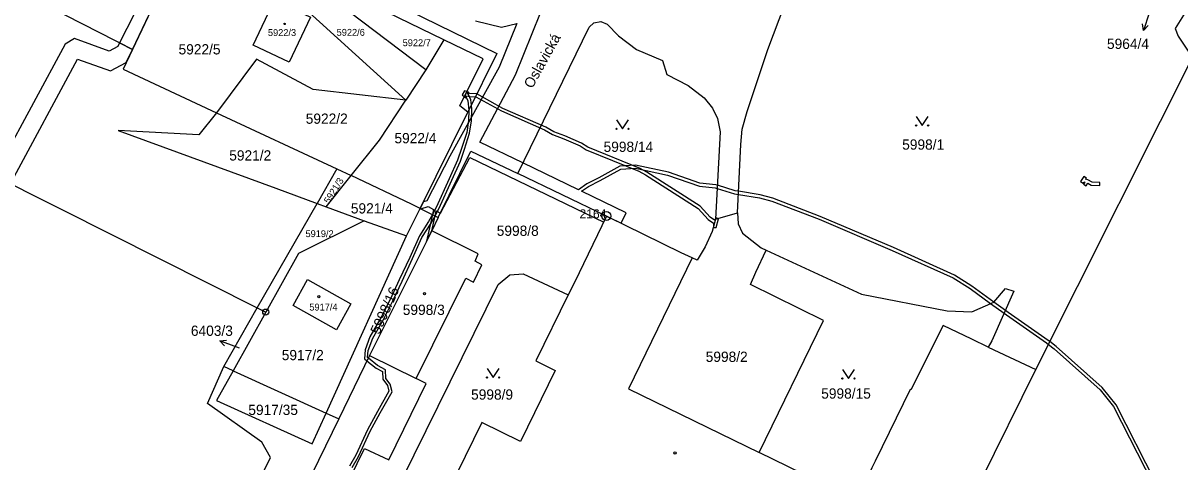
# Model space of a CAD drawing. Extents: x -644096 to -634268, y -1141430 to -1133463.
# Drawn here: x -639819.5 to -639627.9, y -1139025.2 to -1138952.5 of the extents above; entities that cross this region are included whole.
import ezdxf

# ---------------------------------------------------------------- set-up
doc = ezdxf.new("R2010")
doc.units = 0
for name, color, linetype in [('_CIVIL_CONSTRUCTION', 7, 'Continuous'), ('B_Hranice _3D', 7, 'Continuous'), ('M_Svah_Zarez', 7, 'Continuous'), ('svrsek_osa_sjezdy', 7, 'Continuous'), ('svrsek_osa_terminal_VRT', 7, 'Continuous'), ('svrsek_osa_VRT', 7, 'Continuous'), ('svrsek_popisy_VRT', 7, 'Continuous'), ('terminal_VRT', 7, 'Continuous')]:
    doc.layers.add(name, color=color, linetype=linetype)

msp = doc.modelspace()

# ---------------------------------------------------------------- linework, layer by layer
at = {"layer": '_CIVIL_CONSTRUCTION'}
for centre, radius in [((-639722.89, -1138984.51), 0.75), ((-639722.89, -1138984.51), 0.03), ((-639779.29, -1139000.42), 0.5), ((-639779.29, -1139000.42), 0.0303)]:
    msp.add_circle(centre, radius, dxfattribs=at)
at = {"layer": 'B_Hranice _3D'}
for points in [[(-639793.84, -1138936.84), (-639803.5, -1138955.81), (-639801.37, -1138956.9), (-639795.36, -1138944.2)], [(-639626.75, -1138950.35), (-639628.72, -1138953.42), (-639628.21, -1138954.68), (-639626.21, -1138957.66)], [(-639744.57, -1138952.14), (-639740.25, -1138953.22), (-639737.74, -1138952.62), (-639740.63, -1138959.86), (-639748.79, -1138974.59), (-639752.64, -1138981.97), (-639753.18, -1138982.13), (-639753.73, -1138983.24), (-639753.78, -1138983.34), (-639753.63, -1138983.29), (-639752.42, -1138982.95), (-639751.52, -1138983.41), (-639751.7, -1138984.26), (-639752.66, -1138988.66), (-639751.81, -1138986.95), (-639751.25, -1138984.48), (-639751.07, -1138983.64), (-639750.36, -1138984.01), (-639745.51, -1138974.78), (-639723.31, -1138985.5), (-639722.84, -1138984.54), (-639720.46, -1138985.7), (-639719.62, -1138983.96), (-639727, -1138980.39), (-639725.86, -1138979.59), (-639723.92, -1138978.6), (-639720.52, -1138976.74), (-639718.09, -1138976.6), (-639712.76, -1138977.72), (-639707.49, -1138979.54), (-639704.87, -1138979.82), (-639704.53, -1138979.93), (-639701.69, -1138980.8), (-639701.03, -1138980.91), (-639697.53, -1138981.48), (-639695.47, -1138982.05), (-639687.66, -1138985.04), (-639675.54, -1138990.19), (-639665.48, -1138994.72), (-639662.63, -1138996.53), (-639659.26, -1138999), (-639657.03, -1139000.62), (-639656.65, -1139000.9), (-639650.03, -1139005.51), (-639649.7, -1139005.77), (-639648.74, -1139006.52), (-639641.14, -1139013.28), (-639638.91, -1139016.05), (-639632.36, -1139028.94)], [(-639631.9, -1139028.72), (-639638.49, -1139015.77), (-639640.78, -1139012.94), (-639648.42, -1139006.14), (-639649.47, -1139005.31), (-639649.73, -1139005.11), (-639656.35, -1139000.5), (-639656.82, -1139000.16), (-639658.74, -1138998.77), (-639662.35, -1138996.11), (-639665.24, -1138994.28), (-639675.34, -1138989.73), (-639687.48, -1138984.58), (-639695.31, -1138981.57), (-639697.43, -1138981), (-639701.01, -1138980.41), (-639701.57, -1138980.32), (-639704.5, -1138979.4), (-639704.77, -1138979.32), (-639707.39, -1138979.04), (-639712.62, -1138977.24), (-639718.05, -1138976.1), (-639720.66, -1138976.24), (-639724.16, -1138978.16), (-639726.12, -1138979.17), (-639727.52, -1138980.14), (-639736.71, -1138975.7), (-639743.83, -1138972.26), (-639737.91, -1138961.12), (-639733.8, -1138950.84)], [(-639821.33, -1138978.75), (-639810.44, -1138958.49), (-639805.02, -1138960.47), (-639802.4, -1138959.08), (-639801.37, -1138956.9), (-639803.5, -1138955.81), (-639803.81, -1138956.43), (-639805.24, -1138957.19), (-639810.95, -1138955.11), (-639812.53, -1138956.04), (-639822.97, -1138975.47)], [(-639764.98, -1139026.17), (-639763.94, -1139024.34), (-639762, -1139020.16), (-639760.33, -1139017.11), (-639758.36, -1139013.61), (-639758.69, -1139012.37), (-639759.4, -1139011.4), (-639759.44, -1139009.97), (-639760.77, -1139009.27), (-639762.3, -1139008.05), (-639762.42, -1139007.95), (-639762.35, -1139006.79), (-639761.57, -1139004.73), (-639759.82, -1139001.63), (-639758.27, -1138998.55), (-639756.73, -1138995.27), (-639755, -1138991.56), (-639753.42, -1138988.04), (-639751.89, -1138985.67), (-639751.25, -1138984.48), (-639750.61, -1138983.3), (-639748.47, -1138978.54), (-639747.06, -1138975.42), (-639746.37, -1138973.45), (-639745.54, -1138970.79), (-639745.2, -1138968.74), (-639745.14, -1138966.81), (-639745.22, -1138966.13), (-639745.33, -1138965.27), (-639745.72, -1138964.36), (-639746, -1138963.94), (-639746.26, -1138964.46), (-639745.81, -1138965.41), (-639745.65, -1138966.99), (-639745.7, -1138968.7), (-639746.02, -1138970.67), (-639746.85, -1138973.29), (-639747.52, -1138975.24), (-639748.93, -1138978.34), (-639751.05, -1138983.08), (-639751.7, -1138984.26), (-639752.33, -1138985.41), (-639753.86, -1138987.8), (-639755.46, -1138991.36), (-639757.19, -1138995.05), (-639758.71, -1138998.33), (-639760.26, -1139001.39), (-639762.03, -1139004.51), (-639762.85, -1139006.69), (-639762.94, -1139008.17), (-639762.53, -1139008.52), (-639761.03, -1139009.69), (-639759.94, -1139010.27), (-639759.9, -1139011.56), (-639759.15, -1139012.59), (-639758.9, -1139013.55), (-639760.77, -1139016.87), (-639762.44, -1139019.94), (-639764.38, -1139024.12), (-639765.44, -1139025.95)]]:
    msp.add_lwpolyline(points, dxfattribs=at)
for points in [[(-639746.76, -1138964.43), (-639746.39, -1138964.74), (-639745.98, -1138963.89), (-639746.39, -1138963.76)], [(-639717.53, -1138977.07), (-639716.42, -1138977.68), (-639707.68, -1138983.24), (-639706.03, -1138985.1), (-639705.16, -1138985.67), (-639705.14, -1138986.29), (-639705.14, -1138986.38), (-639704.71, -1138986.43), (-639704.34, -1138984.97), (-639704.45, -1138984.92), (-639704.72, -1138984.8), (-639704.98, -1138985.19), (-639705.71, -1138984.72), (-639707.36, -1138982.86), (-639716.16, -1138977.24), (-639717.31, -1138976.61), (-639725.97, -1138973.09), (-639727.01, -1138972.41), (-639729.75, -1138971.24), (-639731.59, -1138970.54), (-639732.93, -1138969.79), (-639740.05, -1138966.66), (-639744.34, -1138964.26), (-639745.58, -1138964.18), (-639745.71, -1138963.98), (-639745.98, -1138963.89), (-639746.39, -1138964.74), (-639746.17, -1138964.93), (-639746, -1138964.59), (-639745.56, -1138964.68), (-639744.48, -1138964.76), (-639740.27, -1138967.1), (-639733.15, -1138970.23), (-639731.81, -1138971), (-639729.93, -1138971.7), (-639727.25, -1138972.85), (-639726.21, -1138973.53)], [(-639641.2, -1138979.43), (-639641.18, -1138978.93), (-639642.47, -1138978.88), (-639643.16, -1138978.51), (-639643.53, -1138978.41), (-639643.4, -1138978.21), (-639643.81, -1138977.94), (-639644.36, -1138978.77), (-639643.95, -1138979.05), (-639643.82, -1138978.85), (-639643.65, -1138978.89), (-639643.87, -1138979.24), (-639643.45, -1138979.51), (-639643.17, -1138979.07), (-639642.61, -1138979.38)]]:
    msp.add_lwpolyline(points, close=True, dxfattribs=at)
at = {"layer": 'M_Svah_Zarez'}
for centre, radius in [((-639776.18, -1138952.68), 0.117), ((-639770.51, -1138997.86), 0.175), ((-639753.01, -1138997.36), 0.175), ((-639711.52, -1139023.76), 0.175)]:
    msp.add_circle(centre, radius, dxfattribs=at)
at = {"layer": 'svrsek_osa_sjezdy'}
for points in [[(-639721.22, -1138968.56), (-639720.22, -1138970.06), (-639719.22, -1138968.56)], [(-639671.59, -1138967.99), (-639670.59, -1138969.49), (-639669.59, -1138967.99)], [(-639742.64, -1139009.76), (-639741.64, -1139011.26), (-639740.64, -1139009.76)], [(-639683.8, -1139009.92), (-639682.8, -1139011.42), (-639681.8, -1139009.92)]]:
    msp.add_lwpolyline(points, dxfattribs=at)
for centre in [(-639671.59, -1138969.49), (-639669.59, -1138969.49), (-639721.22, -1138970.06), (-639719.22, -1138970.06), (-639742.64, -1139011.26), (-639740.64, -1139011.26), (-639683.8, -1139011.42), (-639681.8, -1139011.42)]:
    msp.add_circle(centre, 0.1, dxfattribs=at)
at = {"layer": 'svrsek_osa_terminal_VRT'}
msp.add_arc((-642050.26, -1145189.6), 8802.25, 41.413152, 75.317049, dxfattribs=at)
at = {"layer": 'svrsek_popisy_VRT'}
for p, q in [((-639632.98, -1138950.91), (-639633.96, -1138953.75)), ((-639633.96, -1138953.75), (-639634.1, -1138952.64)), ((-639633.96, -1138953.75), (-639633.16, -1138952.96)), ((-639786.89, -1139005.17), (-639785.78, -1139005.06)), ((-639784.09, -1139006.24), (-639786.89, -1139005.17)), ((-639786.89, -1139005.17), (-639786.14, -1139005.99)), ((-639783.65, -1139006.41), (-639784.09, -1139006.24))]:
    msp.add_line(p, q, dxfattribs=at)
at = {"layer": 'terminal_VRT'}
for p, q in [((-639795.36, -1138944.2), (-639801.37, -1138956.9)), ((-639801.37, -1138956.9), (-639817.92, -1138948.43)), ((-639749.83, -1138955.29), (-639752.8, -1138960.29)), ((-639743.3, -1138958.47), (-639749.83, -1138955.29)), ((-639651.79, -1139009.92), (-639624.22, -1138955.04)), ((-639752.8, -1138960.29), (-639756.08, -1138965.29)), ((-639787.45, -1138967.4), (-639767.51, -1138976.71)), ((-639753.73, -1138983.24), (-639745.81, -1138967.32)), ((-639767.51, -1138976.71), (-639770.78, -1138982.41)), ((-639767.51, -1138976.71), (-639765.17, -1138977.81)), ((-639769.3, -1138982.96), (-639765.17, -1138977.81)), ((-639755.13, -1138982.53), (-639765.17, -1138977.81)), ((-639722.84, -1138984.54), (-639737.56, -1138977.45)), ((-639780.69, -1138999.71), (-639770.78, -1138982.41)), ((-639770.78, -1138982.41), (-639769.3, -1138982.96)), ((-639769.3, -1138982.96), (-639762.99, -1138985.3)), ((-639753.73, -1138983.24), (-639755.13, -1138982.53)), ((-639756, -1138987.81), (-639753.73, -1138983.24)), ((-639753.73, -1138983.24), (-639750.72, -1138984.75)), ((-639750.72, -1138984.75), (-639751.81, -1138986.95)), ((-639704.79, -1138985.02), (-639701.19, -1138984)), ((-639762.99, -1138985.3), (-639756, -1138987.81)), ((-639751.81, -1138986.95), (-639762.1, -1139007.63)), ((-639769.28, -1139017.16), (-639756, -1138987.81)), ((-639786.26, -1139009.43), (-639780.69, -1138999.71)), ((-639780.69, -1138999.71), (-639779.29, -1139000.42)), ((-639779.29, -1139000.42), (-639784.7, -1139010.14)), ((-639762.1, -1139007.63), (-639767.17, -1139018.12)), ((-639762.1, -1139007.63), (-639754.4, -1139011.45)), ((-639659.68, -1139006.23), (-639651.79, -1139009.92)), ((-639784.7, -1139010.14), (-639786.26, -1139009.43)), ((-639660.87, -1139028.37), (-639651.79, -1139009.92)), ((-639784.7, -1139010.14), (-639769.28, -1139017.16)), ((-639769.28, -1139017.16), (-639767.17, -1139018.12)), ((-639767.17, -1139018.12), (-639788, -1139060.58))]:
    msp.add_line(p, q, dxfattribs=at)
for points in [[(-639701.19, -1138984), (-639700.61, -1138972.63), (-639700.39, -1138970.13), (-639699.57, -1138967.19), (-639696.16, -1138956.91), (-639693.31, -1138949.48), (-639692.38, -1138944.61), (-639693.17, -1138938.71), (-639696.92, -1138928.42), (-639699.52, -1138922.11), (-639697.94, -1138920.38)], [(-639927.61, -1138925.81), (-639890.04, -1138944.71), (-639813.05, -1138983.44), (-639780.69, -1138999.71)], [(-639814.49, -1138941.73), (-639805.48, -1138946.03), (-639801.06, -1138937.15), (-639800.05, -1138935.99), (-639798.77, -1138935.09), (-639797.43, -1138934.41), (-639796.03, -1138933.78), (-639794.53, -1138933.33), (-639793, -1138933.22), (-639791.68, -1138933.22), (-639789.95, -1138933.58), (-639741.03, -1138957.6), (-639745.81, -1138967.32)], [(-639749.83, -1138955.29), (-639791.09, -1138935.21), (-639793.88, -1138941.09)], [(-639752.8, -1138960.29), (-639773.88, -1138944.28), (-639793.88, -1138941.09)], [(-639756.08, -1138965.29), (-639775.77, -1138947.43), (-639795.36, -1138944.2)], [(-639777.83, -1138948.69), (-639771.89, -1138951.54), (-639775.42, -1138959), (-639781.39, -1138956.18), (-639777.83, -1138948.69)], [(-639737.56, -1138977.45), (-639732.26, -1138966.6), (-639725.75, -1138953.23), (-639724.96, -1138952.49), (-639723.82, -1138952.27), (-639722.78, -1138952.74), (-639720.87, -1138954.64), (-639717.88, -1138956.9), (-639713.58, -1138958.76), (-639712.85, -1138961.03), (-639709.36, -1138962.85), (-639706.7, -1138964.93), (-639705.32, -1138966.65), (-639704.49, -1138968.36), (-639704.05, -1138970.58), (-639704.79, -1138985.02)], [(-639801.37, -1138956.9), (-639802.93, -1138960.19), (-639787.45, -1138967.4)], [(-639756.08, -1138965.29), (-639771.46, -1138963.55), (-639780.82, -1138958.54), (-639787.45, -1138967.4)], [(-639745.81, -1138967.32), (-639747.14, -1138966.25), (-639743.3, -1138958.47)], [(-639765.17, -1138977.81), (-639760.46, -1138971.93), (-639756.08, -1138965.29)], [(-639787.45, -1138967.4), (-639790.35, -1138971.04), (-639803.72, -1138970.33), (-639777.65, -1138979.87), (-639770.78, -1138982.41)], [(-639750.72, -1138984.75), (-639745.32, -1138973.76), (-639737.56, -1138977.45)], [(-639722.84, -1138984.54), (-639728.19, -1138995.5), (-639729.2, -1138997.57)], [(-639708.67, -1138991.45), (-639710.5, -1138990.58), (-639722.84, -1138984.54)], [(-639704.79, -1138985.02), (-639705.36, -1138987.07), (-639706.55, -1138989.6), (-639707.83, -1138991.81), (-639708.67, -1138991.45)], [(-639701.19, -1138984), (-639701.04, -1138985.78), (-639700.32, -1138987.32), (-639697.25, -1138989.77), (-639696.41, -1138990.16)], [(-639762.99, -1138985.3), (-639773.88, -1138990.69), (-639779.29, -1139000.42)], [(-639754.4, -1139011.45), (-639746.14, -1138994.81), (-639744.89, -1138995.46), (-639743.49, -1138992.59), (-639744.59, -1138991.97), (-639744.09, -1138990.79), (-639751.81, -1138986.95)], [(-639697.6, -1139023.7), (-639686.94, -1139001.79), (-639699.02, -1138995.86), (-639698.11, -1138993.8), (-639696.41, -1138990.16)], [(-639696.41, -1138990.16), (-639680.66, -1138997.44), (-639666.43, -1139000.2), (-639662.39, -1139000.36), (-639658.74, -1138998.77), (-639656.79, -1138996.5), (-639655.4, -1138996.96), (-639659.05, -1139005.16), (-639659.68, -1139006.23)], [(-639708.67, -1138991.45), (-639719.21, -1139013.13), (-639697.6, -1139023.7)], [(-639764.42, -1139063.79), (-639767.3, -1139061.41), (-639769.28, -1139056.87), (-639768.6, -1139052.3), (-639740.79, -1138995.84), (-639738.85, -1138994.25), (-639736.69, -1138994.1), (-639729.2, -1138997.57)], [(-639774.78, -1138999.34), (-639772.37, -1138995.02), (-639765.18, -1138999.05), (-639767.55, -1139003.37), (-639774.78, -1138999.34)], [(-639729.2, -1138997.57), (-639734.58, -1139008.51), (-639731.36, -1139010.12), (-639737.09, -1139021.84), (-639743.53, -1139018.69), (-639760.02, -1139052.41), (-639758.92, -1139052.95), (-639763.74, -1139062.72)], [(-639659.68, -1139006.23), (-639662.37, -1139004.91), (-639667.11, -1139002.66), (-639672.46, -1139013.3), (-639672.57, -1139013.24), (-639678.38, -1139025.13), (-639678.93, -1139026.25), (-639683.67, -1139035.95), (-639687.75, -1139033.95), (-639685.62, -1139029.53), (-639697.6, -1139023.7)], [(-639788, -1139060.58), (-639791.91, -1139051.44), (-639778.49, -1139024.49), (-639779.95, -1139022), (-639788.94, -1139015.56), (-639786.26, -1139009.43)], [(-639784.7, -1139010.14), (-639787.44, -1139015.07), (-639771.59, -1139022.25), (-639769.28, -1139017.16)], [(-639729.07, -1139080.81), (-639730.71, -1139084.18), (-639776.89, -1139061.42), (-639780.84, -1139059.66), (-639762.94, -1139023.02), (-639758.92, -1139024.88), (-639752.72, -1139012.28), (-639754.4, -1139011.45)]]:
    msp.add_lwpolyline(points, dxfattribs=at)

# ---------------------------------------------------------------- texts
at = {"layer": '_CIVIL_CONSTRUCTION'}
msp.add_text('2164', height=1.5, dxfattribs=at).set_placement((-639727.34, -1138984.89))
at = {"layer": 'svrsek_osa_VRT'}
for s, height, p in [('5922/3', 1.14, (-639778.93, -1138954.68)), ('5922/6', 1.14, (-639767.55, -1138954.64)), ('5922/5', 1.7, (-639793.73, -1138957.73)), ('5922/7', 1.14, (-639756.62, -1138956.36)), ('5964/4', 1.7, (-639639.99, -1138956.82)), ('5922/2', 1.7, (-639772.67, -1138969.22)), ('5922/4', 1.7, (-639757.98, -1138972.45)), ('5921/2', 1.7, (-639785.34, -1138975.31)), ('5998/14', 1.7, (-639723.35, -1138973.88)), ('5998/1', 1.7, (-639673.9, -1138973.51)), ('5921/4', 1.7, (-639765.2, -1138984.08)), ('5919/2', 1.14, (-639772.71, -1138988)), ('5998/8', 1.7, (-639741.04, -1138987.79)), ('5917/4', 1.14, (-639772.07, -1139000.17)), ('5998/3', 1.7, (-639756.6, -1139000.89)), ('6403/3', 1.7, (-639791.69, -1139004.36)), ('5917/2', 1.7, (-639776.64, -1139008.39)), ('5998/2', 1.7, (-639706.44, -1139008.67)), ('5998/9', 1.7, (-639745.29, -1139014.93)), ('5998/15', 1.7, (-639687.31, -1139014.76)), ('5917/35', 1.7, (-639782.18, -1139017.47))]:
    msp.add_text(s, height=height, dxfattribs=at).set_placement(p)
for s, height, rotation, p in [('5921/3', 1.14, 58, (-639768.79, -1138982.56)), ('5998/16', 1.7, 66, (-639760.5, -1139004.24))]:
    msp.add_text(s, height=height, rotation=rotation, dxfattribs=at).set_placement(p)
at = {"layer": 'svrsek_popisy_VRT'}
msp.add_text('Oslavická', height=1.7, rotation=61, dxfattribs=at).set_placement((-639735.17, -1138963.5))

doc.saveas('drawing.dxf')
